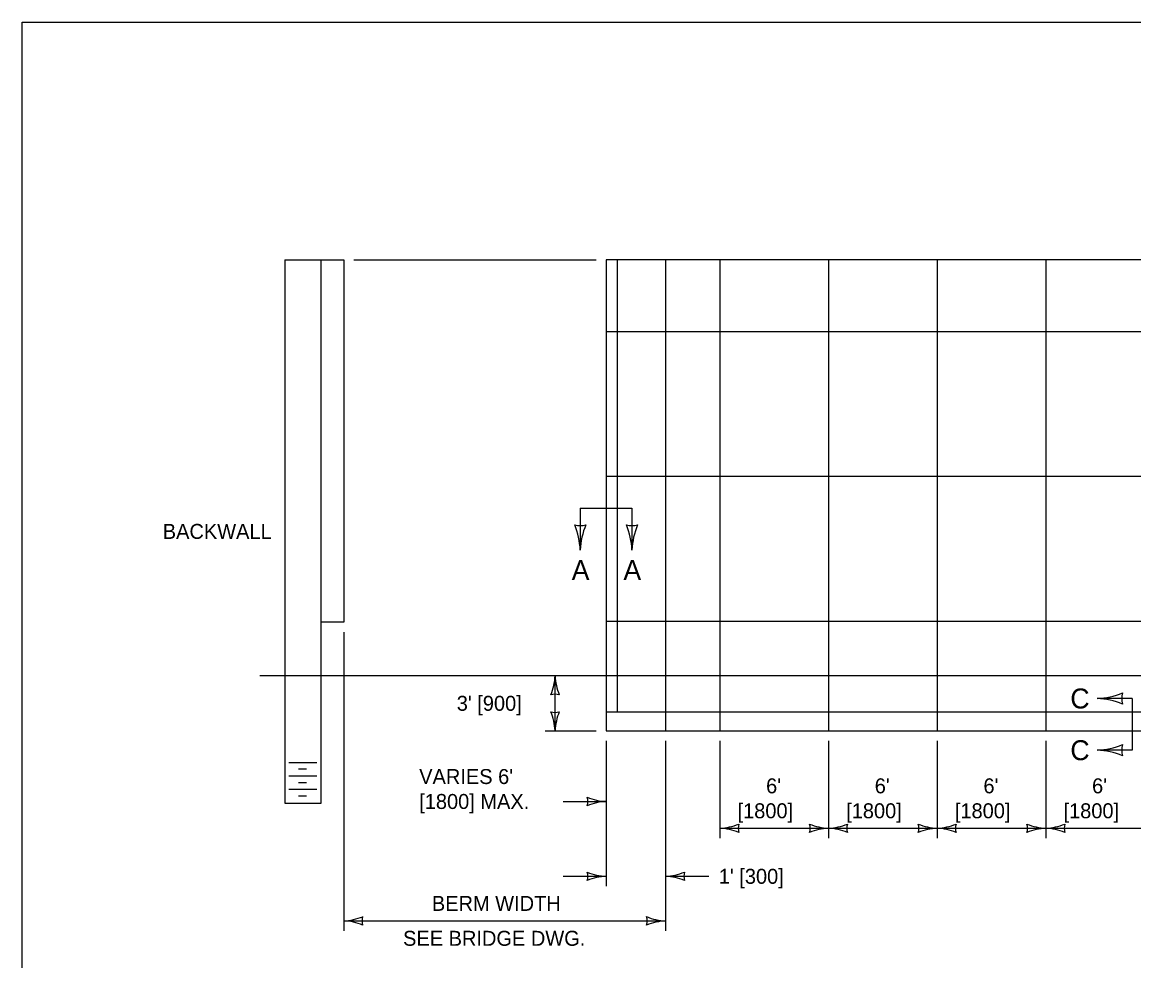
# Model space of a CAD drawing. Extents: x 49991.4 to 50021, y 49987.6 to 50011.4.
# Drawn here: x 49999.384 to 50003.843, y 49995.236 to 49998.999 of the extents above; entities that cross this region are included whole.
import ezdxf

# ---------------------------------------------------------------- set-up
doc = ezdxf.new("R2010")
doc.units = 0
for name, color, linetype in [('Level 1', 7, 'Continuous'), ('Level 2', 7, 'Continuous'), ('Level 3', 7, 'Continuous'), ('Level 4', 7, 'Continuous'), ('Level 5', 7, 'Continuous'), ('Level 6', 7, 'Continuous')]:
    doc.layers.add(name, color=color, linetype=linetype)

msp = doc.modelspace()

# ---------------------------------------------------------------- linework, layer by layer
at = {"layer": 'Level 1'}
for p, q in [((50000.4371, 49998.0473), (50000.4371, 49995.8682)), ((50000.4371, 49998.0473), (50000.5824, 49998.0473)), ((50000.5824, 49995.8682), (50000.5824, 49998.0473)), ((50000.5824, 49998.0473), (50000.6732, 49998.0473)), ((50000.6732, 49998.0473), (50000.6732, 49996.5945)), ((50004.4142, 49998.0473), (50001.7265, 49998.0473)), ((50001.7265, 49998.0473), (50001.7265, 49996.1588)), ((50001.9646, 49998.0473), (50001.9646, 49996.1588)), ((50002.1825, 49998.0473), (50002.1825, 49996.1588)), ((50002.6181, 49998.0473), (50002.6181, 49996.1588)), ((50003.0542, 49998.0473), (50003.0542, 49996.1588)), ((50003.4902, 49998.0473), (50003.4902, 49996.1588)), ((50004.3599, 49997.7584), (50001.7265, 49997.7584)), ((50004.3599, 49997.1775), (50001.7265, 49997.1775)), ((50000.6732, 49996.5945), (50000.5824, 49996.5945)), ((50004.3599, 49996.596), (50001.7296, 49996.596)), ((50004.4142, 49996.2328), (50001.7265, 49996.2328)), ((50001.7265, 49996.1588), (50004.4142, 49996.1588)), ((50000.4532, 49996.0316), (50000.5651, 49996.0316)), ((50000.4912, 49996.0053), (50000.5239, 49996.0053)), ((50000.4532, 49995.9774), (50000.5651, 49995.9774)), ((50000.4532, 49995.9247), (50000.5651, 49995.9247)), ((50000.4912, 49995.9511), (50000.5239, 49995.9511)), ((50000.4371, 49995.8682), (50000.5824, 49995.8682)), ((50000.4912, 49995.8982), (50000.5239, 49995.8982))]:
    msp.add_line(p, q, dxfattribs=at)
msp.add_lwpolyline([(49999.3835, 49998.9992), (50016.7501, 49998.9992), (50016.7501, 49987.7988), (49999.3835, 49987.7988)], close=True, dxfattribs=at)
at = {"layer": 'Level 3'}
for p, q in [((50000.6732, 49996.5545), (50000.6732, 49995.3564)), ((50001.5213, 49996.1588), (50001.5213, 49996.3785)), ((50001.4813, 49996.1588), (50001.6865, 49996.1588)), ((50001.7265, 49996.1188), (50001.7265, 49995.535)), ((50001.9646, 49996.1188), (50001.9646, 49995.3564)), ((50002.1825, 49996.1188), (50002.1825, 49995.7277)), ((50002.6181, 49996.1188), (50002.6181, 49995.7277)), ((50003.0542, 49996.1188), (50003.0542, 49995.7277)), ((50003.4902, 49996.1188), (50003.4902, 49995.7277)), ((50001.5531, 49995.875), (50001.7265, 49995.875)), ((50002.1825, 49995.7677), (50002.6181, 49995.7677)), ((50002.6181, 49995.7677), (50003.0542, 49995.7677)), ((50003.0542, 49995.7677), (50003.4902, 49995.7677)), ((50003.4902, 49995.7677), (50003.9259, 49995.7677)), ((50001.5531, 49995.575), (50001.7265, 49995.575)), ((50001.9646, 49995.575), (50002.138, 49995.575)), ((50000.6732, 49995.3964), (50001.9646, 49995.3964))]:
    msp.add_line(p, q, dxfattribs=at)
for centre, radius, start, end in [((50001.6222, 49997.054), 0.073, 252.1388, 287.8612), ((50001.3119, 49996.8677), 0.3107, 2.8273, 22.0772), ((50001.9184, 49996.8708), 0.2964, 157.456, 177.6395), ((50001.8297, 49997.054), 0.073, 252.1388, 287.8612), ((50001.5194, 49996.8677), 0.3107, 2.8273, 22.0772), ((50002.1259, 49996.8708), 0.2964, 157.456, 177.6395), ((50001.2992, 49996.3877), 0.2223, 337.456, 357.6395), ((50001.754, 49996.39), 0.233, 182.8273, 202.0772), ((50001.5213, 49996.2503), 0.0548, 72.1388, 107.8612), ((50003.681, 49996.5982), 0.3107, 272.8273, 292.0772), ((50003.6841, 49995.9917), 0.2964, 67.456, 87.6395), ((50003.8673, 49996.2879), 0.073, 162.1388, 197.8612), ((50001.5213, 49996.287), 0.0548, 252.1388, 287.8612), ((50001.2886, 49996.1473), 0.233, 2.8273, 22.0772), ((50001.7434, 49996.1496), 0.2223, 157.456, 177.6395), ((50003.681, 49996.3909), 0.3107, 272.8273, 292.0772), ((50003.8673, 49996.0806), 0.073, 162.1388, 197.8612), ((50003.6841, 49995.7844), 0.2964, 67.456, 87.6395), ((50001.7357, 49996.0971), 0.2223, 247.456, 267.6395), ((50001.5983, 49995.875), 0.0548, 342.1388, 17.8612), ((50001.738, 49995.6423), 0.233, 92.8273, 112.0772), ((50002.171, 49996.0004), 0.233, 272.8273, 292.0772), ((50002.3107, 49995.7677), 0.0548, 162.1388, 197.8612), ((50002.6273, 49995.9898), 0.2223, 247.456, 267.6395), ((50002.4899, 49995.7677), 0.0548, 342.1388, 17.8612), ((50002.6066, 49996.0004), 0.233, 272.8273, 292.0772), ((50002.7463, 49995.7677), 0.0548, 162.1388, 197.8612), ((50003.0634, 49995.9898), 0.2223, 247.456, 267.6395), ((50002.926, 49995.7677), 0.0548, 342.1388, 17.8612), ((50003.0427, 49996.0004), 0.233, 272.8273, 292.0772), ((50003.1824, 49995.7677), 0.0548, 162.1388, 197.8612), ((50003.4994, 49995.9898), 0.2223, 247.456, 267.6395), ((50003.362, 49995.7677), 0.0548, 342.1388, 17.8612), ((50003.4787, 49996.0004), 0.233, 272.8273, 292.0772), ((50003.6184, 49995.7677), 0.0548, 162.1388, 197.8612), ((50002.1733, 49995.5456), 0.2223, 67.456, 87.6395), ((50002.6296, 49995.535), 0.233, 92.8273, 112.0772), ((50002.6089, 49995.5456), 0.2223, 67.456, 87.6395), ((50003.0657, 49995.535), 0.233, 92.8273, 112.0772), ((50003.045, 49995.5456), 0.2223, 67.456, 87.6395), ((50003.5017, 49995.535), 0.233, 92.8273, 112.0772), ((50003.481, 49995.5456), 0.2223, 67.456, 87.6395), ((50001.7357, 49995.7971), 0.2223, 247.456, 267.6395), ((50001.5983, 49995.575), 0.0548, 342.1388, 17.8612), ((50001.738, 49995.3423), 0.233, 92.8273, 112.0772), ((50001.9531, 49995.8077), 0.233, 272.8273, 292.0772), ((50001.9554, 49995.3529), 0.2223, 67.456, 87.6395), ((50002.0928, 49995.575), 0.0548, 162.1388, 197.8612), ((50000.6617, 49995.6291), 0.233, 272.8273, 292.0772), ((50000.664, 49995.1743), 0.2223, 67.456, 87.6395), ((50000.8014, 49995.3964), 0.0548, 162.1388, 197.8612), ((50001.9738, 49995.6185), 0.2223, 247.456, 267.6395), ((50001.8364, 49995.3964), 0.0548, 342.1388, 17.8612), ((50001.9761, 49995.1637), 0.233, 92.8273, 112.0772)]:
    msp.add_arc(centre, radius, start, end, dxfattribs=at)
at = {"layer": 'Level 4'}
msp.add_line((50001.7721, 49996.2328), (50001.7721, 49998.0473), dxfattribs=at)
at = {"layer": 'Level 5'}
for p, q in [((50000.7132, 49998.0473), (50001.6865, 49998.0473)), ((50004.6227, 49996.3785), (50000.3371, 49996.3785))]:
    msp.add_line(p, q, dxfattribs=at)
at = {"layer": 'Level 6'}
for p, q in [((50001.6222, 49997.0505), (50001.6222, 49996.883)), ((50001.6222, 49997.0505), (50001.8297, 49997.0505)), ((50001.8297, 49997.0505), (50001.8297, 49996.883)), ((50003.8358, 49996.2879), (50003.6963, 49996.2879)), ((50003.8358, 49996.2879), (50003.8358, 49996.0806)), ((50003.8358, 49996.0806), (50003.6963, 49996.0806))]:
    msp.add_line(p, q, dxfattribs=at)

# ---------------------------------------------------------------- texts
at = {"layer": 'Level 2'}
for s, height, p in [('BACKWALL', 0.06, (49999.9473, 49996.9278)), ('A', 0.08, (50001.5878, 49996.763)), ('A', 0.08, (50001.7953, 49996.763)), ("3' [900]", 0.06, (50001.1268, 49996.2386)), ("VARIES 6'", 0.06, (50000.9761, 49995.945)), ("6'", 0.06, (50002.3678, 49995.9077)), ("6'", 0.06, (50002.8036, 49995.9077)), ("6'", 0.06, (50003.2397, 49995.9077)), ("6'", 0.06, (50003.6755, 49995.9077)), ('[1800] MAX.', 0.06, (50000.9761, 49995.845)), ('[1800]', 0.06, (50002.2531, 49995.8077)), ('[1800]', 0.06, (50002.689, 49995.8077)), ('[1800]', 0.06, (50003.125, 49995.8077)), ('[1800]', 0.06, (50003.5609, 49995.8077)), ("1' [300]", 0.06, (50002.178, 49995.545)), ('BERM WIDTH', 0.06, (50001.0269, 49995.4364)), ('SEE BRIDGE DWG.', 0.06, (50000.9114, 49995.2964))]:
    msp.add_text(s, height=height, dxfattribs=at).set_placement(p)
for rotation, p in [(360, (50003.5883, 49996.2479)), (0, (50003.5883, 49996.0406))]:
    msp.add_text('C', height=0.08, rotation=rotation, dxfattribs=at).set_placement(p)

doc.saveas('drawing.dxf')
